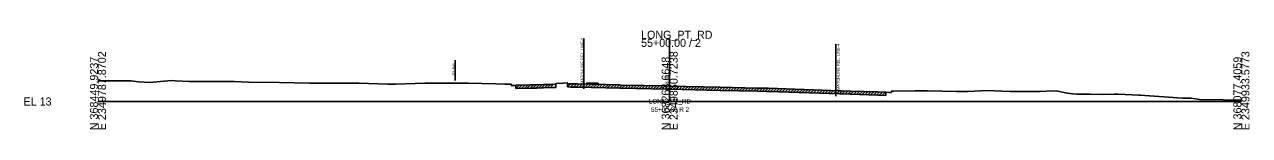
# Model space of a CAD drawing. Extents: x 974 to 2350744, y -10 to 368509.
# Drawn here: x 1974.3 to 2402.8, y 1990.3 to 2024.7 of the extents above; entities that cross this region are included whole.
import ezdxf

# ---------------------------------------------------------------- set-up
doc = ezdxf.new("R2010")
doc.units = 0
for name, color, linetype in [('RD_GPK_XS_Cell', 7, 'Continuous'), ('RD_PD_ConcMed', 7, 'Continuous'), ('RD_XS_CurbTop', 7, 'Continuous'), ('RD_XS_ExGround', 7, 'Continuous'), ('RD_XS_ExPaveRet', 7, 'Continuous'), ('RD_XS_ExRW', 7, 'Continuous'), ('RD_XS_MatchLine', 7, 'Continuous'), ('RD_XS_TX_Elev_EX', 7, 'Continuous'), ('RD_XS_TX_Station', 7, 'Continuous')]:
    doc.layers.add(name, color=color, linetype=linetype)

msp = doc.modelspace()

# ---------------------------------------------------------------- linework, layer by layer
at = {"layer": 'RD_GPK_XS_Cell'}
for p, q in [((2200, 2000), (2200, 2021.84)), ((2000, 2000), (2200, 2000)), ((2200, 2000), (2400, 2000))]:
    msp.add_line(p, q, dxfattribs=at)
at = {"layer": 'RD_PD_ConcMed'}
for p, q in [((2171, 2006.04), (2171, 2006.54)), ((2171, 2006.54), (2175, 2006.44)), ((2175, 2005.94), (2175, 2006.44))]:
    msp.add_line(p, q, dxfattribs=at)
at = {"layer": 'RD_XS_CurbTop'}
msp.add_line((2176, 2005.92), (2176, 2005.9), dxfattribs=at)
at = {"layer": 'RD_XS_ExGround'}
msp.add_lwpolyline([(2000, 2007.15), (2000.84, 2007.22), (2011.45, 2007.18), (2014.36, 2006.84), (2017.98, 2006.68), (2025.75, 2007.28), (2027.06, 2007.25), (2031.98, 2006.93), (2035.97, 2006.99), (2041.99, 2007.02), (2047.71, 2006.99), (2052.69, 2006.72), (2063.49, 2006.63), (2073.98, 2006.39), (2075.67, 2006.4), (2076.57, 2006.36), (2077.29, 2006.35), (2088.25, 2006.35), (2091.38, 2006.37), (2101.24, 2006.02), (2104.14, 2006.02), (2114.34, 2006.37), (2115.09, 2006.36), (2115.84, 2006.35), (2129.64, 2006.36), (2134.34, 2006.31), (2139.22, 2006.15), (2142.38, 2006.09), (2144.01, 2006.06), (2144.51, 2006.06), (2144.67, 2005.56), (2145.77, 2005.62), (2146.17, 2005.64), (2151.19, 2005.77), (2153.5, 2005.82), (2155.81, 2005.9), (2159.1, 2005.98), (2159.83, 2006.01), (2160.18, 2006.02), (2160.34, 2006.32), (2162.77, 2006.43), (2164.15, 2006.51), (2164.31, 2006.21), (2165.3, 2006.19), (2167.73, 2006.13), (2182.51, 2005.76), (2183.08, 2005.74), (2198.87, 2005.43), (2200, 2005.4), (2217.52, 2004.98), (2230.78, 2004.69), (2233.87, 2004.66), (2234.6, 2004.66), (2259.57, 2003.77), (2260.06, 2003.77), (2263.13, 2003.66), (2272.84, 2003.36), (2275.58, 2003.24), (2276.95, 2003.17), (2277.47, 2003.15), (2277.68, 2003.64), (2278.32, 2003.64), (2285.94, 2003.69), (2289.5, 2003.71), (2290.18, 2003.76), (2300.44, 2003.53), (2300.88, 2003.52), (2301.18, 2003.52), (2304.33, 2003.5), (2310.91, 2003.88), (2319.08, 2003.5), (2319.91, 2003.44), (2323, 2003.44), (2329.05, 2003.49), (2329.46, 2003.51), (2334.29, 2003.7), (2335.8, 2003.62), (2339.11, 2002.92), (2341.05, 2002.69), (2342.4, 2002.57), (2347.13, 2002.55), (2351.47, 2002.5), (2355.49, 2002.53), (2357.01, 2002.53), (2364.07, 2002.26), (2364.62, 2002.23), (2379.37, 2001.11), (2382.39, 2001.15), (2385.35, 2000.71), (2393.68, 2000.55), (2398.67, 2000.51), (2400, 2000.51)], dxfattribs=at)
at = {"layer": 'RD_XS_ExPaveRet'}
for p, q in [((2146.17, 2004.5), (2147.34, 2005.67)), ((2146.17, 2004.5), (2146.17, 2005.64)), ((2147.17, 2004.53), (2148.34, 2005.7)), ((2148.17, 2004.55), (2149.34, 2005.72)), ((2149.17, 2004.57), (2150.34, 2005.75)), ((2150.17, 2004.6), (2151.34, 2005.77)), ((2151.17, 2004.62), (2152.34, 2005.8)), ((2152.17, 2004.65), (2153.34, 2005.82)), ((2153.17, 2004.67), (2154.35, 2005.85)), ((2154.17, 2004.7), (2155.35, 2005.89)), ((2155.17, 2004.74), (2156.34, 2005.91)), ((2156.17, 2004.77), (2157.34, 2005.94)), ((2157.17, 2004.79), (2158.34, 2005.96)), ((2158.17, 2004.81), (2159.34, 2005.99)), ((2160.18, 2006.02), (2160.18, 2004.88)), ((2164.31, 2005.07), (2164.31, 2006.21)), ((2164.31, 2005.07), (2165.43, 2006.18)), ((2165.31, 2005.04), (2166.43, 2006.16)), ((2166.31, 2005.02), (2167.43, 2006.13)), ((2167.31, 2004.99), (2168.43, 2006.11)), ((2168.31, 2004.97), (2169.43, 2006.08)), ((2169.31, 2004.94), (2170.43, 2006.06)), ((2170.31, 2004.92), (2171.43, 2006.03)), ((2171.31, 2004.89), (2172.43, 2006.01)), ((2172.31, 2004.87), (2173.43, 2005.98)), ((2173.31, 2004.84), (2174.43, 2005.96)), ((2174.31, 2004.82), (2175.43, 2005.93)), ((2175.31, 2004.79), (2176.43, 2005.91)), ((2176.31, 2004.77), (2177.43, 2005.88)), ((2177.31, 2004.74), (2178.43, 2005.86)), ((2178.31, 2004.72), (2179.43, 2005.83)), ((2179.31, 2004.69), (2180.43, 2005.81)), ((2180.31, 2004.67), (2181.43, 2005.78)), ((2181.31, 2004.64), (2182.43, 2005.76)), ((2182.31, 2004.62), (2183.43, 2005.74)), ((2183.31, 2004.6), (2184.44, 2005.72)), ((2184.31, 2004.58), (2185.44, 2005.7)), ((2185.31, 2004.56), (2186.44, 2005.68)), ((2186.31, 2004.54), (2187.44, 2005.66)), ((2187.31, 2004.52), (2188.44, 2005.64)), ((2188.31, 2004.5), (2189.44, 2005.62)), ((2189.31, 2004.48), (2190.44, 2005.6)), ((2190.31, 2004.46), (2191.44, 2005.58)), ((2191.31, 2004.44), (2192.44, 2005.56)), ((2192.31, 2004.42), (2193.44, 2005.54)), ((2146.17, 2004.5), (2151.19, 2004.62)), ((2151.19, 2004.62), (2153.5, 2004.68)), ((2153.5, 2004.68), (2155.81, 2004.76)), ((2155.81, 2004.76), (2159.1, 2004.84)), ((2159.1, 2004.84), (2159.83, 2004.87)), ((2159.83, 2004.87), (2160.18, 2004.88)), ((2164.31, 2005.07), (2165.3, 2005.04)), ((2165.3, 2005.04), (2167.73, 2004.98)), ((2167.73, 2004.98), (2182.51, 2004.61)), ((2182.51, 2004.61), (2183.08, 2004.6)), ((2183.08, 2004.6), (2198.87, 2004.29)), ((2193.31, 2004.4), (2194.44, 2005.52)), ((2194.31, 2004.38), (2195.44, 2005.5)), ((2195.31, 2004.36), (2196.44, 2005.48)), ((2196.31, 2004.34), (2197.44, 2005.46)), ((2197.31, 2004.32), (2198.44, 2005.44)), ((2198.31, 2004.3), (2199.43, 2005.42)), ((2198.87, 2004.29), (2200, 2004.26)), ((2199.31, 2004.28), (2200.43, 2005.39)), ((2200, 2004.26), (2217.52, 2003.83)), ((2200.31, 2004.25), (2201.43, 2005.37)), ((2201.31, 2004.23), (2202.43, 2005.34)), ((2202.31, 2004.2), (2203.43, 2005.32)), ((2203.31, 2004.18), (2204.43, 2005.3)), ((2204.31, 2004.16), (2205.43, 2005.27)), ((2205.31, 2004.13), (2206.43, 2005.25)), ((2206.31, 2004.11), (2207.43, 2005.22)), ((2207.31, 2004.08), (2208.43, 2005.2)), ((2208.31, 2004.06), (2209.43, 2005.17)), ((2209.31, 2004.03), (2210.43, 2005.15)), ((2210.31, 2004.01), (2211.43, 2005.13)), ((2211.31, 2003.99), (2212.43, 2005.1)), ((2212.31, 2003.96), (2213.43, 2005.08)), ((2213.31, 2003.94), (2214.43, 2005.05)), ((2214.31, 2003.91), (2215.43, 2005.03)), ((2215.31, 2003.89), (2216.43, 2005)), ((2216.31, 2003.86), (2217.43, 2004.98)), ((2217.31, 2003.84), (2218.43, 2004.96)), ((2217.52, 2003.83), (2230.78, 2003.55)), ((2218.31, 2003.82), (2219.43, 2004.94)), ((2219.31, 2003.8), (2220.43, 2004.91)), ((2220.31, 2003.77), (2221.43, 2004.89)), ((2221.31, 2003.75), (2222.43, 2004.87)), ((2222.31, 2003.73), (2223.43, 2004.85)), ((2223.31, 2003.71), (2224.43, 2004.83)), ((2224.31, 2003.69), (2225.43, 2004.81)), ((2225.31, 2003.67), (2226.43, 2004.78)), ((2226.31, 2003.64), (2227.43, 2004.76)), ((2227.31, 2003.62), (2228.43, 2004.74)), ((2228.31, 2003.6), (2229.43, 2004.72)), ((2229.31, 2003.58), (2230.43, 2004.7)), ((2230.31, 2003.56), (2231.44, 2004.68)), ((2230.78, 2003.55), (2233.87, 2003.52)), ((2231.31, 2003.54), (2232.45, 2004.68)), ((2232.31, 2003.53), (2233.45, 2004.67)), ((2233.31, 2003.53), (2234.45, 2004.66)), ((2233.87, 2003.52), (2234.6, 2003.52)), ((2234.31, 2003.52), (2235.43, 2004.63)), ((2234.6, 2003.52), (2259.57, 2002.63)), ((2235.31, 2003.49), (2236.42, 2004.6)), ((2236.31, 2003.46), (2237.42, 2004.56)), ((2237.31, 2003.42), (2238.42, 2004.53)), ((2238.31, 2003.39), (2239.42, 2004.49)), ((2239.31, 2003.35), (2240.42, 2004.45)), ((2240.31, 2003.31), (2241.42, 2004.42)), ((2241.31, 2003.28), (2242.42, 2004.38)), ((2242.31, 2003.24), (2243.42, 2004.35)), ((2243.31, 2003.21), (2244.42, 2004.31)), ((2244.31, 2003.17), (2245.42, 2004.28)), ((2245.31, 2003.14), (2246.42, 2004.24)), ((2246.31, 2003.1), (2247.42, 2004.2)), ((2247.31, 2003.06), (2248.42, 2004.17)), ((2248.31, 2003.03), (2249.42, 2004.13)), ((2249.31, 2002.99), (2250.42, 2004.1)), ((2250.31, 2002.96), (2251.42, 2004.06)), ((2251.31, 2002.92), (2252.42, 2004.02)), ((2252.31, 2002.89), (2253.42, 2003.99)), ((2253.31, 2002.85), (2254.42, 2003.95)), ((2254.31, 2002.81), (2255.42, 2003.92)), ((2255.31, 2002.78), (2256.42, 2003.88)), ((2256.31, 2002.74), (2257.42, 2003.85)), ((2257.31, 2002.71), (2258.42, 2003.81)), ((2258.31, 2002.67), (2259.42, 2003.77)), ((2259.31, 2002.63), (2260.43, 2003.75)), ((2259.57, 2002.63), (2260.06, 2002.62)), ((2260.06, 2002.62), (2263.13, 2002.52)), ((2260.31, 2002.62), (2261.42, 2003.72)), ((2261.31, 2002.58), (2262.42, 2003.69)), ((2262.31, 2002.55), (2263.42, 2003.66)), ((2263.13, 2002.52), (2272.84, 2002.21)), ((2263.31, 2002.52), (2264.42, 2003.62)), ((2264.31, 2002.48), (2265.42, 2003.59)), ((2265.31, 2002.45), (2266.42, 2003.56)), ((2266.31, 2002.42), (2267.42, 2003.53)), ((2267.31, 2002.39), (2268.42, 2003.5)), ((2268.31, 2002.36), (2269.42, 2003.46)), ((2269.31, 2002.32), (2270.42, 2003.43)), ((2270.31, 2002.29), (2271.42, 2003.4)), ((2271.31, 2002.26), (2272.42, 2003.37)), ((2272.31, 2002.23), (2273.42, 2003.33)), ((2272.84, 2002.21), (2275.58, 2002.09)), ((2273.31, 2002.19), (2274.41, 2003.29)), ((2274.31, 2002.15), (2275.41, 2003.24)), ((2275.58, 2003.24), (2275.58, 2002.09))]:
    msp.add_line(p, q, dxfattribs=at)
at = {"layer": 'RD_XS_ExRW'}
msp.add_line((2125, 2007.36), (2125, 2014.36), dxfattribs=at)
at = {"layer": 'RD_XS_MatchLine'}
for p, q in [((2170, 2021.98), (2170, 2004.38)), ((2258.18, 2019.93), (2258.18, 2001.81))]:
    msp.add_line(p, q, dxfattribs=at)

# ---------------------------------------------------------------- texts
at = {"layer": 'RD_GPK_XS_Cell'}
for s, p in [('LONG_PT_RD', (2190, 2021.84)), ('55+00.00 / 2', (2190, 2019.04)), ('EL 13', (1974, 1998.6))]:
    msp.add_text(s, height=2.8, dxfattribs=at).set_placement(p)
for s, p in [('N 368449.9237', (2000, 1990)), ('E 2349787.8702', (2002.8, 1990)), ('N 368263.6648', (2200, 1990)), ('E 2349860.7238', (2202.8, 1990)), ('N 368077.4059', (2400, 1990)), ('E 2349933.5773', (2402.8, 1990))]:
    msp.add_text(s, height=2.8, rotation=90, dxfattribs=at).set_placement(p)
at = {"layer": 'RD_XS_ExRW'}
msp.add_text('EX. R/W ', height=0.75, rotation=90, dxfattribs=at).set_placement((2124.75, 2009.31))
at = {"layer": 'RD_XS_MatchLine'}
for s, p in [('MATCHLINE REL. LINE-2', (2169.92, 2006.1)), ('MATCHLINE REL. LINE-4', (2259.5, 2003.98))]:
    msp.add_text(s, height=1, rotation=90, dxfattribs=at).set_placement(p)
at = {"layer": 'RD_XS_TX_Elev_EX'}
msp.add_text('18.40', height=1, rotation=90, dxfattribs=at).set_placement((2199.51, 2005.4))
at = {"layer": 'RD_XS_TX_Station'}
for s, p in [('LONG_PT_RD', (2192.72, 1999.3)), ('55+00.00 R 2', (2193.48, 1996.4))]:
    msp.add_text(s, height=1.6, dxfattribs=at).set_placement(p)

doc.saveas('drawing.dxf')
